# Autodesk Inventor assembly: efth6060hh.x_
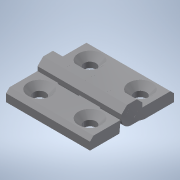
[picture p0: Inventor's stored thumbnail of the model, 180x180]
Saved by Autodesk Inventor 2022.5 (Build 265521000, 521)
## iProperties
Part Number: efth6060hh.x_
Material: 一般
Document SubType Name: Assembly
Designer: ImaoCorp
Sending System: SOLIDWORKS 2017-2017317
MC: AMD64
MC_MODEL: Intel64 Family 6 Model 60 Stepping 3, GenuineIntel
OS: Windows_NT
FRU: Parasolid Version 29.0, build 201,  4-17-2017
FORMAT: text
GUISE: transmit
KEY: efth6060hh
FILE: efth6060hh.x_t
DATE: Mon May 13 14:22:09 2019
Author: ImaoCorp
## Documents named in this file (4)
- X:\14_SW2022-Inv2022\00_全2023-1023新製品(TCC)まで\e\efth6060hh\EFTH6060HH.iam
- X:\14_SW2022-Inv2022\00_全2023-1023新製品(TCC)まで\e\efth6060hh\efth6060hh_01.ipt
- X:\14_SW2022-Inv2022\00_全2023-1023新製品(TCC)まで\e\efth6060hh\efth6060hh_02.ipt
- X:\14_SW2022-Inv2022\00_全2023-1023新製品(TCC)まで\e\efth6060hh\efth6060hh_03.ipt
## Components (3 placed, 3 different names)
1. efth6060hh_01
2. efth6060hh_02
3. efth6060hh_03
